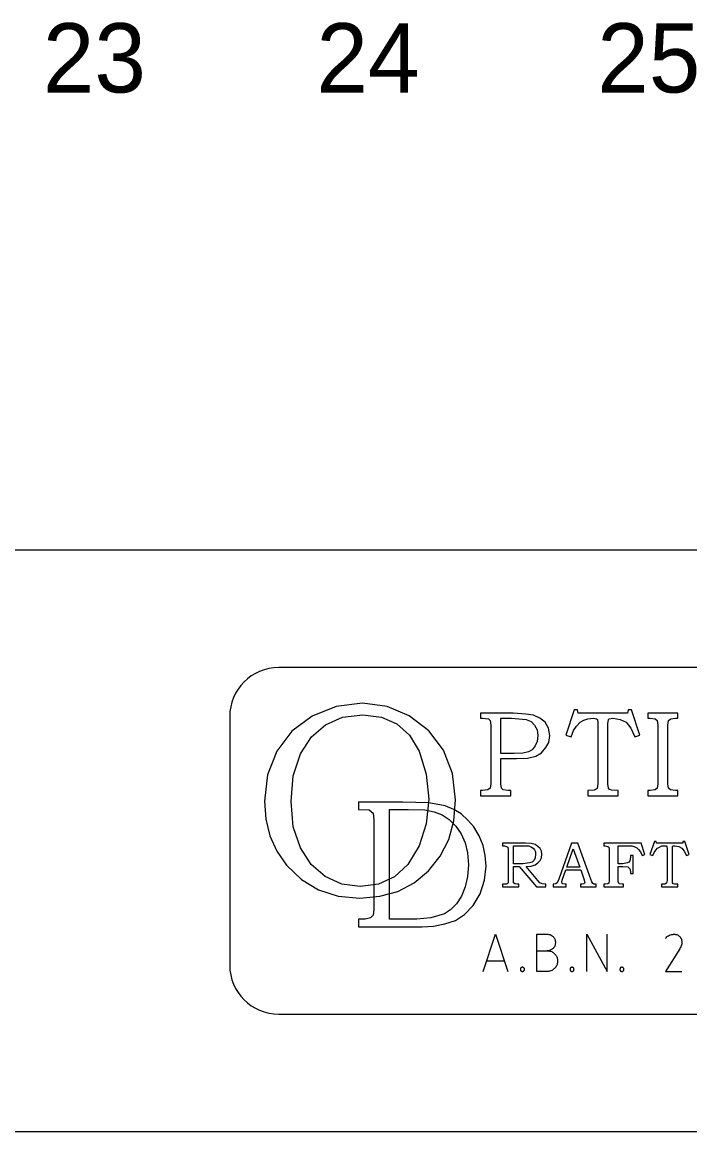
# Model space of a CAD drawing. Extents: x 0 to 841, y 0 to 594.
# Drawn here: x 495 to 543.2, y 15 to 95.1 of the extents above; entities that cross this region are included whole.
import ezdxf

# ---------------------------------------------------------------- set-up
doc = ezdxf.new("R2010")
doc.units = 0
for name, color, linetype in [('A1BORDER', 7, 'Continuous'), ('Level 1', 7, 'Continuous'), ('Level 10', 7, 'Continuous')]:
    doc.layers.add(name, color=color, linetype=linetype)

msp = doc.modelspace()

# ---------------------------------------------------------------- linework, layer by layer
at = {"layer": 'A1BORDER'}
for p, q in [((28, 57), (829, 57)), ((829, 15), (28, 15))]:
    msp.add_line(p, q, dxfattribs=at)
at = {"layer": 'Level 1'}
for points in [[(519.59, 45.93), (517.69, 45.7), (515.96, 45), (514.48, 43.9), (513.4, 42.47), (512.73, 40.77), (512.5, 38.87), (512.6, 37.57), (512.9, 36.37), (513.39, 35.25), (514.1, 34.25), (515.17, 33.2), (516.4, 32.45), (517.82, 32), (519.4, 31.87), (520.84, 32), (522.14, 32.35), (523.32, 32.97), (524.34, 33.83), (525.19, 34.9), (525.8, 36.1), (526.17, 37.45), (526.28, 38.95), (526.07, 40.85), (525.42, 42.53), (524.37, 43.93), (522.94, 45.03), (521.36, 45.7)], [(519.6, 45.1), (520.96, 44.93), (522.06, 44.45), (522.96, 43.63), (523.66, 42.47), (524.18, 40.8), (524.36, 39), (524.18, 37.23), (523.66, 35.63), (522.86, 34.3), (521.88, 33.4), (520.73, 32.87), (519.42, 32.7), (518.08, 32.87), (516.88, 33.43), (515.88, 34.3), (515.1, 35.5), (514.59, 37), (514.43, 38.83), (514.59, 40.7), (515.1, 42.27), (515.89, 43.5), (516.9, 44.37), (518.14, 44.93)], [(519.3, 38.25), (520.07, 38.23), (520.34, 38), (520.4, 37.5), (520.4, 31.07), (520.36, 30.63), (520.16, 30.43), (519.78, 30.35), (519.67, 30.35), (519.3, 30.35), (519.3, 29.8), (523.88, 29.8), (524.7, 29.85), (525.53, 30), (526.28, 30.25), (526.93, 30.67), (527.56, 31.33), (528.06, 32.17), (528.38, 33.15), (528.5, 34.17), (528.44, 34.95), (528.28, 35.67), (528, 36.37), (527.62, 37), (527.18, 37.5), (526.7, 37.95), (526.16, 38.27), (525.54, 38.53), (524.36, 38.73), (522.5, 38.8), (519.3, 38.8)], [(521.52, 30.35), (521.52, 38.25), (522.88, 38.25), (524.09, 38.23), (524.74, 38.1), (525.32, 37.87), (525.84, 37.53), (526.32, 37.05), (526.7, 36.5), (526.99, 35.85), (527.16, 35.13), (527.22, 34.27), (527.16, 33.43), (526.99, 32.67), (526.72, 32), (526.36, 31.45), (525.93, 31.03), (525.5, 30.73), (524.52, 30.45), (523.5, 30.35)], [(529.69, 35.83), (529.69, 35.63), (529.82, 35.63), (529.98, 35.6), (530.06, 35.55), (530.09, 35.37), (530.09, 33.13), (530.08, 32.97), (530.03, 32.9), (529.96, 32.87), (529.8, 32.87), (529.69, 32.87), (529.69, 32.67), (530.86, 32.67), (530.86, 32.87), (530.77, 32.87), (530.56, 32.9), (530.48, 32.97), (530.47, 33.13), (530.47, 34.15), (530.89, 34.15), (532.13, 32.67), (532.8, 32.67), (532.8, 32.87), (532.74, 32.87), (532.54, 32.9), (532.37, 32.97), (532.23, 33.13), (531.38, 34.15), (531.74, 34.17), (532.03, 34.27), (532.24, 34.4), (532.4, 34.57), (532.49, 34.77), (532.52, 35.03), (532.49, 35.25), (532.4, 35.45), (532.24, 35.6), (532.04, 35.73), (531.74, 35.8), (531.33, 35.83)], [(530.47, 35.63), (531.33, 35.63), (531.59, 35.63), (531.77, 35.55), (531.89, 35.47), (531.99, 35.35), (532.06, 35.2), (532.07, 35), (532.04, 34.77), (531.97, 34.6), (531.82, 34.47), (531.64, 34.4), (531.16, 34.35), (530.47, 34.35)], [(534.66, 35.83), (533.74, 33.23), (533.63, 32.97), (533.53, 32.9), (533.34, 32.87), (533.34, 32.67), (534.27, 32.67), (534.27, 32.87), (534.18, 32.87), (534.03, 32.9), (533.98, 32.93), (533.96, 33.03), (533.98, 33.17), (534.24, 33.9), (535.33, 33.9), (535.56, 33.25), (535.63, 33), (535.6, 32.95), (535.56, 32.9), (535.42, 32.87), (535.3, 32.87), (535.3, 32.67), (536.44, 32.67), (536.44, 32.87), (536.39, 32.87), (536.28, 32.87), (536.2, 32.93), (536.13, 33.05), (536.06, 33.23), (535.12, 35.83)], [(534.32, 34.1), (534.78, 35.43), (535.26, 34.1)], [(536.99, 35.83), (536.99, 35.63), (537.1, 35.63), (537.28, 35.6), (537.36, 35.55), (537.38, 35.37), (537.38, 33.13), (537.36, 32.95), (537.28, 32.9), (537.08, 32.87), (536.99, 32.87), (536.99, 32.67), (538.4, 32.67), (538.4, 32.87), (538.32, 32.87), (538.13, 32.9), (538.06, 32.97), (538.02, 33.13), (538.02, 34.15), (538.37, 34.15), (538.72, 34.13), (538.87, 33.97), (538.9, 33.87), (538.92, 33.75), (538.92, 33.65), (539.1, 33.65), (539.1, 34.93), (538.92, 34.93), (538.92, 34.85), (538.9, 34.67), (538.87, 34.55), (538.79, 34.45), (538.69, 34.4), (538.34, 34.35), (538.02, 34.35), (538.02, 35.63), (538.72, 35.63), (539.02, 35.63), (539.22, 35.57), (539.37, 35.5), (539.5, 35.37), (539.63, 35.2), (539.76, 34.93), (539.96, 35), (539.69, 35.83)], [(540.64, 35.95), (540.32, 35), (540.52, 34.93), (540.62, 35.15), (540.74, 35.33), (540.87, 35.47), (541, 35.55), (541.17, 35.63), (541.38, 35.63), (541.49, 35.63), (541.53, 35.57), (541.56, 35.45), (541.56, 33.13), (541.52, 32.95), (541.4, 32.87), (541.16, 32.87), (541.16, 32.67), (542.32, 32.67), (542.32, 32.87), (542.08, 32.87), (541.99, 32.9), (541.94, 32.97), (541.94, 33.13), (541.94, 35.43), (541.94, 35.6), (541.97, 35.63), (542.12, 35.63), (542.4, 35.6), (542.63, 35.47), (542.8, 35.25), (542.96, 34.93), (543.16, 35), (542.84, 35.95), (542.7, 35.95), (542.69, 35.83), (540.79, 35.83), (540.77, 35.95)]]:
    msp.add_lwpolyline(points, close=True, dxfattribs=at)
for points in [[(528.28, 26.57), (529.18, 29.26), (530.07, 26.57)], [(532.17, 28.06), (532.9, 28.06), (532.98, 28.06), (533.04, 28.06), (533.1, 28.04), (533.17, 28.03), (533.23, 28), (533.28, 27.96), (533.34, 27.93), (533.39, 27.89), (533.44, 27.85), (533.48, 27.8), (533.52, 27.75), (533.56, 27.69), (533.59, 27.64), (533.62, 27.57), (533.63, 27.51), (533.64, 27.45), (533.66, 27.39), (533.66, 27.33), (533.66, 27.25), (533.64, 27.19), (533.63, 27.13), (533.62, 27.06), (533.59, 27), (533.56, 26.95), (533.52, 26.89), (533.48, 26.84), (533.44, 26.79), (533.39, 26.75), (533.34, 26.71), (533.28, 26.67), (533.23, 26.64), (533.17, 26.61), (533.1, 26.6), (533.04, 26.59), (532.98, 26.57), (532.9, 26.57), (532.17, 26.57), (532.17, 29.26), (532.9, 29.26), (532.96, 29.26), (533.02, 29.25), (533.07, 29.24), (533.12, 29.23), (533.17, 29.2), (533.2, 29.19), (533.26, 29.15), (533.29, 29.13), (533.33, 29.09), (533.37, 29.05), (533.4, 29.01), (533.43, 28.96), (533.46, 28.91), (533.47, 28.86), (533.49, 28.81), (533.49, 28.77), (533.5, 28.71), (533.5, 28.66), (533.5, 28.61), (533.49, 28.56), (533.49, 28.51), (533.47, 28.46), (533.46, 28.41), (533.43, 28.36), (533.4, 28.33), (533.37, 28.27), (533.33, 28.24), (533.29, 28.2), (533.26, 28.17), (533.2, 28.15), (533.17, 28.13), (533.12, 28.1), (533.07, 28.09), (533.02, 28.07), (532.96, 28.06), (532.9, 28.06)], [(535.76, 26.57), (535.76, 29.26), (537.24, 26.57), (537.24, 29.26)], [(541.43, 28.96), (541.48, 29.01), (541.53, 29.07), (541.59, 29.11), (541.67, 29.15), (541.73, 29.19), (541.8, 29.21), (541.88, 29.24), (541.96, 29.25), (542.03, 29.26), (542.07, 29.26), (542.12, 29.26), (542.17, 29.25), (542.22, 29.24), (542.27, 29.23), (542.3, 29.21), (542.36, 29.19), (542.39, 29.16), (542.43, 29.13), (542.47, 29.1), (542.49, 29.05), (542.53, 29.01), (542.56, 28.97), (542.57, 28.94), (542.59, 28.89), (542.6, 28.84), (542.62, 28.79), (542.62, 28.75), (542.62, 28.7), (542.62, 28.66), (542.62, 28.57), (542.59, 28.5), (542.57, 28.43), (542.54, 28.35), (542.5, 28.27), (542.48, 28.21), (541.43, 26.57), (542.62, 26.57)], [(528.58, 27.33), (529.77, 27.33)], [(530.97, 26.73), (530.97, 26.71), (530.97, 26.7), (530.97, 26.69), (530.98, 26.67), (530.98, 26.66), (530.98, 26.65), (530.99, 26.64), (530.99, 26.63), (531, 26.61), (531.02, 26.61), (531.03, 26.6), (531.04, 26.59), (531.06, 26.59), (531.07, 26.59), (531.08, 26.57), (531.09, 26.57), (531.1, 26.57), (531.12, 26.57), (531.13, 26.57), (531.14, 26.57), (531.16, 26.57), (531.17, 26.59), (531.18, 26.59), (531.19, 26.59), (531.2, 26.6), (531.2, 26.61), (531.22, 26.61), (531.23, 26.63), (531.23, 26.64), (531.24, 26.65), (531.26, 26.66), (531.26, 26.67), (531.26, 26.69), (531.27, 26.7), (531.27, 26.71), (531.27, 26.73), (531.27, 26.74), (531.27, 26.75), (531.26, 26.76), (531.26, 26.77), (531.26, 26.79), (531.24, 26.8), (531.23, 26.81), (531.23, 26.81), (531.22, 26.83), (531.2, 26.84), (531.2, 26.85), (531.19, 26.85), (531.18, 26.86), (531.17, 26.86), (531.16, 26.86), (531.14, 26.87), (531.13, 26.87), (531.12, 26.87), (531.1, 26.87), (531.09, 26.87), (531.08, 26.86), (531.07, 26.86), (531.06, 26.86), (531.04, 26.85), (531.03, 26.85), (531.02, 26.84), (531, 26.83), (530.99, 26.81), (530.99, 26.81), (530.98, 26.8), (530.98, 26.79), (530.98, 26.77), (530.97, 26.76), (530.97, 26.75), (530.97, 26.74), (530.97, 26.73)], [(534.56, 26.73), (534.56, 26.71), (534.56, 26.7), (534.56, 26.69), (534.56, 26.67), (534.57, 26.66), (534.57, 26.65), (534.58, 26.64), (534.58, 26.63), (534.59, 26.61), (534.6, 26.61), (534.62, 26.6), (534.63, 26.59), (534.64, 26.59), (534.64, 26.59), (534.66, 26.57), (534.68, 26.57), (534.69, 26.57), (534.7, 26.57), (534.72, 26.57), (534.73, 26.57), (534.74, 26.57), (534.76, 26.59), (534.77, 26.59), (534.78, 26.59), (534.78, 26.6), (534.79, 26.61), (534.8, 26.61), (534.82, 26.63), (534.82, 26.64), (534.83, 26.65), (534.83, 26.66), (534.84, 26.67), (534.84, 26.69), (534.84, 26.7), (534.84, 26.71), (534.86, 26.73), (534.84, 26.74), (534.84, 26.75), (534.84, 26.76), (534.84, 26.77), (534.83, 26.79), (534.83, 26.8), (534.82, 26.81), (534.82, 26.81), (534.8, 26.83), (534.79, 26.84), (534.78, 26.85), (534.78, 26.85), (534.77, 26.86), (534.76, 26.86), (534.74, 26.86), (534.73, 26.87), (534.72, 26.87), (534.7, 26.87), (534.69, 26.87), (534.68, 26.87), (534.66, 26.86), (534.64, 26.86), (534.64, 26.86), (534.63, 26.85), (534.62, 26.85), (534.6, 26.84), (534.59, 26.83), (534.58, 26.81), (534.58, 26.81), (534.57, 26.8), (534.57, 26.79), (534.56, 26.77), (534.56, 26.76), (534.56, 26.75), (534.56, 26.74), (534.56, 26.73)], [(538.14, 26.73), (538.14, 26.71), (538.14, 26.7), (538.14, 26.69), (538.16, 26.67), (538.16, 26.66), (538.16, 26.65), (538.17, 26.64), (538.17, 26.63), (538.18, 26.61), (538.19, 26.61), (538.2, 26.6), (538.22, 26.59), (538.23, 26.59), (538.24, 26.59), (538.26, 26.57), (538.27, 26.57), (538.28, 26.57), (538.29, 26.57), (538.3, 26.57), (538.32, 26.57), (538.33, 26.57), (538.34, 26.59), (538.36, 26.59), (538.37, 26.59), (538.38, 26.6), (538.38, 26.61), (538.39, 26.61), (538.4, 26.63), (538.4, 26.64), (538.42, 26.65), (538.43, 26.66), (538.43, 26.67), (538.43, 26.69), (538.44, 26.7), (538.44, 26.71), (538.44, 26.73), (538.44, 26.74), (538.44, 26.75), (538.43, 26.76), (538.43, 26.77), (538.43, 26.79), (538.42, 26.8), (538.4, 26.81), (538.4, 26.81), (538.39, 26.83), (538.38, 26.84), (538.38, 26.85), (538.37, 26.85), (538.36, 26.86), (538.34, 26.86), (538.33, 26.86), (538.32, 26.87), (538.3, 26.87), (538.29, 26.87), (538.28, 26.87), (538.27, 26.87), (538.26, 26.86), (538.24, 26.86), (538.23, 26.86), (538.22, 26.85), (538.2, 26.85), (538.19, 26.84), (538.18, 26.83), (538.17, 26.81), (538.17, 26.81), (538.16, 26.8), (538.16, 26.79), (538.16, 26.77), (538.14, 26.76), (538.14, 26.75), (538.14, 26.74), (538.14, 26.73)]]:
    msp.add_lwpolyline(points, dxfattribs=at)
at = {"layer": 'Level 10'}
for p, q in [((571.47, 48.5), (513.54, 48.5)), ((510, 44.97), (510, 27.03)), ((513.54, 23.5), (571.47, 23.5)), ((513.54, 23.5), (513.54, 23.5))]:
    msp.add_line(p, q, dxfattribs=at)
for points in [[(528.1, 45.2), (528.1, 44.85), (528.24, 44.85), (528.66, 44.8), (528.79, 44.67), (528.84, 44.35), (528.84, 40.1), (528.79, 39.8), (528.63, 39.67), (528.24, 39.63), (528.1, 39.63), (528.1, 39.25), (530.29, 39.25), (530.29, 39.63), (530.1, 39.63), (529.74, 39.67), (529.6, 39.8), (529.57, 40.1), (529.57, 41.93), (530.68, 41.93), (531.49, 41.97), (532.08, 42.1), (532.49, 42.35), (532.82, 42.73), (533.02, 43.1), (533.09, 43.6), (533, 44.13), (532.76, 44.55), (532.38, 44.85), (531.92, 45.07), (531.36, 45.15), (530.46, 45.2)], [(529.57, 44.85), (530.34, 44.85), (531.4, 44.75), (531.74, 44.6), (532, 44.35), (532.19, 44), (532.24, 43.6), (532.19, 43.17), (532.04, 42.85), (531.82, 42.57), (531.56, 42.43), (531.14, 42.33), (530.53, 42.3), (529.57, 42.3)], [(534.86, 45.45), (534.26, 43.63), (534.63, 43.5), (534.8, 43.95), (535.03, 44.27), (535.28, 44.55), (535.54, 44.7), (535.84, 44.8), (536.26, 44.85), (536.47, 44.8), (536.53, 44.75), (536.56, 44.5), (536.56, 40.1), (536.5, 39.77), (536.29, 39.65), (535.83, 39.63), (535.83, 39.25), (538.02, 39.25), (538.02, 39.63), (537.56, 39.65), (537.4, 39.7), (537.32, 39.8), (537.29, 40.1), (537.29, 44.43), (537.32, 44.75), (537.37, 44.8), (537.64, 44.85), (538.18, 44.75), (538.6, 44.55), (538.94, 44.13), (539.22, 43.5), (539.59, 43.63), (538.99, 45.45), (538.74, 45.45), (538.7, 45.2), (535.14, 45.2), (535.1, 45.45)], [(540.16, 45.2), (540.16, 44.85), (540.33, 44.85), (540.69, 44.8), (540.83, 44.67), (540.88, 44.35), (540.88, 40.1), (540.83, 39.8), (540.69, 39.67), (540.33, 39.63), (540.16, 39.63), (540.16, 39.25), (542.33, 39.25), (542.33, 39.63), (542.16, 39.63), (541.8, 39.67), (541.66, 39.8), (541.6, 40.1), (541.6, 44.35), (541.66, 44.67), (541.82, 44.8), (542.16, 44.85), (542.33, 44.85), (542.33, 45.2)]]:
    msp.add_lwpolyline(points, close=True, dxfattribs=at)
for centre, start, end in [((513.53545, 44.96253), 90, 180), ((513.53545, 27.03003), 180, 270)]:
    msp.add_arc(centre, 3.535, start, end, dxfattribs=at)

# ---------------------------------------------------------------- texts
at = {"layer": 'Level 1'}
for s, p in [('23', (496.52, 90)), ('24', (516.26, 90)), ('25', (536.52, 90))]:
    msp.add_text(s, height=4.99998, dxfattribs=at).set_placement(p)

doc.saveas('drawing.dxf')
